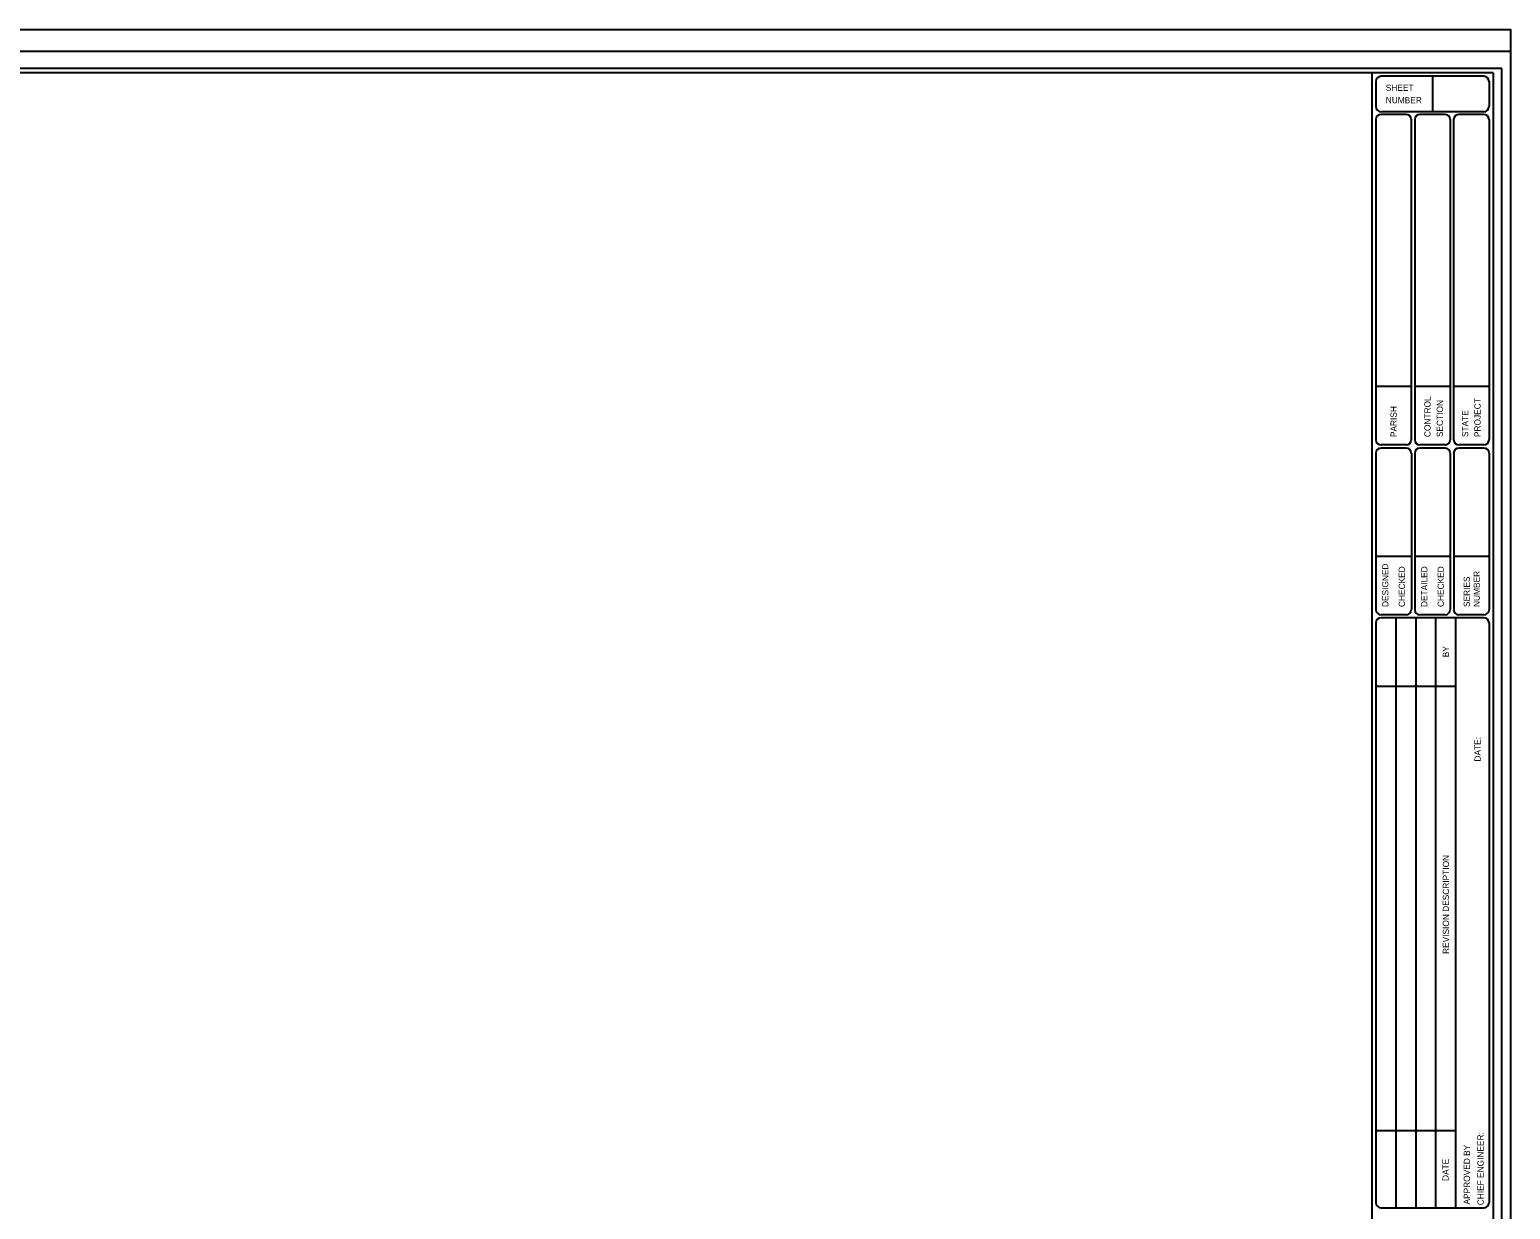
# Model space of a CAD drawing. Extents: x -2.5 to 31.7, y -0.7 to 21.7.
# Drawn here: x 14.59 to 31.7, y 7.86 to 21.5 of the extents above; entities that cross this region are included whole.
import ezdxf

# ---------------------------------------------------------------- set-up
doc = ezdxf.new("R2010")
doc.units = 0
for name, color, linetype in [('Plot Border', 7, 'Continuous'), ('Plot Border 2', 7, 'Continuous'), ('Sheet Border', 7, 'Continuous')]:
    doc.layers.add(name, color=color, linetype=linetype)

msp = doc.modelspace()

# ---------------------------------------------------------------- linework, layer by layer
at = {"layer": 'Plot Border'}
for points in [[(-2.3, 21.5), (31.7, 21.5), (31.7, -0.5), (-2.3, -0.5)], [(31.6, 21.05), (-1.4, 21.05), (-1.4, -0.05), (31.6, -0.05)]]:
    msp.add_lwpolyline(points, close=True, dxfattribs=at)
at = {"layer": 'Plot Border 2'}
msp.add_lwpolyline([(-2.3, 21.25), (31.7, 21.25), (31.7, -0.25), (-2.3, -0.25)], close=True, dxfattribs=at)
at = {"layer": 'Sheet Border'}
for p, q in [((31.5, 21), (0, 21)), ((30.1, 21), (30.1, 0)), ((30.146, 20.901), (30.146, 20.611)), ((31.394, 20.96), (30.206, 20.96)), ((30.8, 20.96), (30.8, 20.551)), ((31.454, 20.901), (31.454, 20.611)), ((31.5, 21), (31.5, 0)), ((31.394, 20.551), (30.206, 20.551)), ((30.146, 20.464), (30.146, 16.754)), ((30.496, 20.52), (30.206, 20.52)), ((30.555, 20.465), (30.555, 16.754)), ((30.595, 20.46), (30.595, 16.759)), ((30.945, 20.52), (30.654, 20.52)), ((31.005, 20.461), (31.005, 16.758)), ((31.044, 20.46), (31.044, 16.759)), ((31.394, 20.52), (31.104, 20.52)), ((31.454, 20.46), (31.454, 16.759)), ((30.555, 17.373), (30.146, 17.373)), ((31.005, 17.373), (30.595, 17.373)), ((31.454, 17.373), (31.044, 17.373)), ((30.146, 16.608), (30.146, 14.796)), ((30.496, 16.699), (30.206, 16.699)), ((30.496, 16.663), (30.206, 16.663)), ((30.556, 16.603), (30.556, 14.796)), ((30.595, 16.608), (30.595, 14.796)), ((30.945, 16.699), (30.654, 16.699)), ((30.946, 16.663), (30.655, 16.663)), ((31.005, 16.603), (31.005, 14.796)), ((31.045, 16.608), (31.045, 14.796)), ((31.394, 16.699), (31.104, 16.699)), ((31.395, 16.663), (31.104, 16.663)), ((31.454, 16.603), (31.454, 14.796)), ((30.555, 15.41), (30.146, 15.41)), ((31.005, 15.41), (30.595, 15.41)), ((31.454, 15.41), (31.044, 15.41)), ((30.496, 14.736), (30.206, 14.736)), ((30.946, 14.736), (30.655, 14.736)), ((31.395, 14.736), (31.104, 14.736)), ((30.146, 14.643), (30.146, 7.941)), ((31.394, 14.701), (30.206, 14.701)), ((30.376, 14.701), (30.376, 7.882)), ((30.606, 14.701), (30.606, 7.882)), ((30.836, 14.701), (30.836, 7.882)), ((31.065, 14.701), (31.065, 7.882)), ((31.454, 14.643), (31.454, 7.941)), ((31.065, 13.909), (30.146, 13.909)), ((30.146, 8.776), (31.065, 8.776)), ((30.206, 7.882), (31.394, 7.882))]:
    msp.add_line(p, q, dxfattribs=at)
for centre, start, end in [((30.206, 20.901), 90, 180), ((31.394, 20.901), 0, 90), ((30.206, 20.61), 180, 270), ((31.394, 20.61), 270, 0), ((30.206, 20.46), 90, 180), ((30.496, 20.46), 0, 90), ((30.655, 20.46), 90, 180), ((30.945, 20.46), 0, 90), ((31.104, 20.46), 90, 180), ((31.394, 20.46), 0, 90), ((30.206, 16.759), 180, 270), ((30.206, 16.604), 90, 180), ((30.496, 16.759), 270, 0), ((30.496, 16.604), 0, 90), ((30.655, 16.759), 180, 270), ((30.655, 16.604), 90, 180), ((30.945, 16.759), 270, 0), ((30.945, 16.604), 0, 90), ((31.104, 16.759), 180, 270), ((31.104, 16.604), 90, 180), ((31.394, 16.759), 270, 0), ((31.395, 16.604), 0, 90), ((30.206, 14.795), 180, 270), ((30.496, 14.795), 270, 0), ((30.655, 14.795), 180, 270), ((30.945, 14.795), 270, 0), ((31.104, 14.795), 180, 270), ((31.395, 14.795), 270, 0), ((30.206, 14.643), 90, 180), ((31.394, 14.643), 0, 90), ((30.206, 7.941), 180, 270), ((31.394, 7.941), 270, 0)]:
    msp.add_arc(centre, 0.0594, start, end, dxfattribs=at)

# ---------------------------------------------------------------- texts
for s, p in [('SHEET', (30.26, 20.792)), ('NUMBER', (30.26, 20.649))]:
    msp.add_text(s, height=0.072, dxfattribs=at).set_placement(p)
for s, p in [('PARISH', (30.387, 16.79)), ('CONTROL', (30.778, 16.79)), ('SECTION', (30.921, 16.79)), ('PROJECT', (31.356, 16.79)), ('STATE', (31.213, 16.79)), ('DESIGNED', (30.291, 14.826)), ('CHECKED', (30.482, 14.826)), ('DETAILED', (30.741, 14.826)), ('CHECKED', (30.931, 14.826)), ('NUMBER', (31.347, 14.826)), ('SERIES', (31.232, 14.826)), ('BY', (30.991, 14.245)), ('DATE:', (31.357, 13.04)), ('REVISION DESCRIPTION', (30.991, 10.816)), ('CHIEF ENGINEER:', (31.391, 7.911)), ('APPROVED BY', (31.233, 7.92)), ('DATE', (30.987, 8.192))]:
    msp.add_text(s, height=0.072, rotation=90, dxfattribs=at).set_placement(p)

doc.saveas('drawing.dxf')
